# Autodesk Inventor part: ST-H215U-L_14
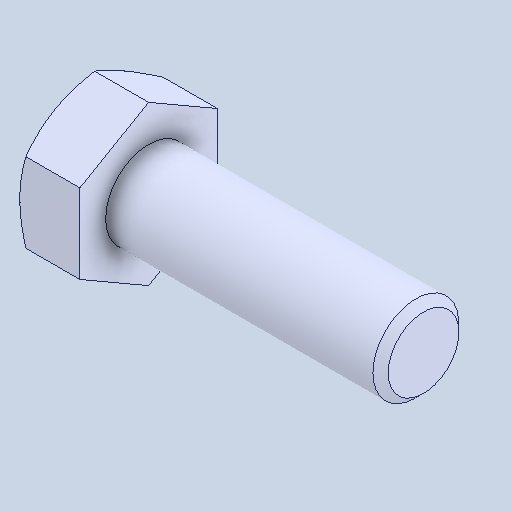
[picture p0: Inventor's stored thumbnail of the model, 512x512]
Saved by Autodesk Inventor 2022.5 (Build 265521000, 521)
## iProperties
Created: 2024-07
Part Number: ST-H215U-L_14
Material: 一般
Document SubType Name: Modeling
Designer: ImaoCorp
Density: 1 g/cm^3
Appearance: 既定
Author: ImaoCorp
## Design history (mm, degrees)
feature "ST-H215U-L_14"
node "ソリッド1"
